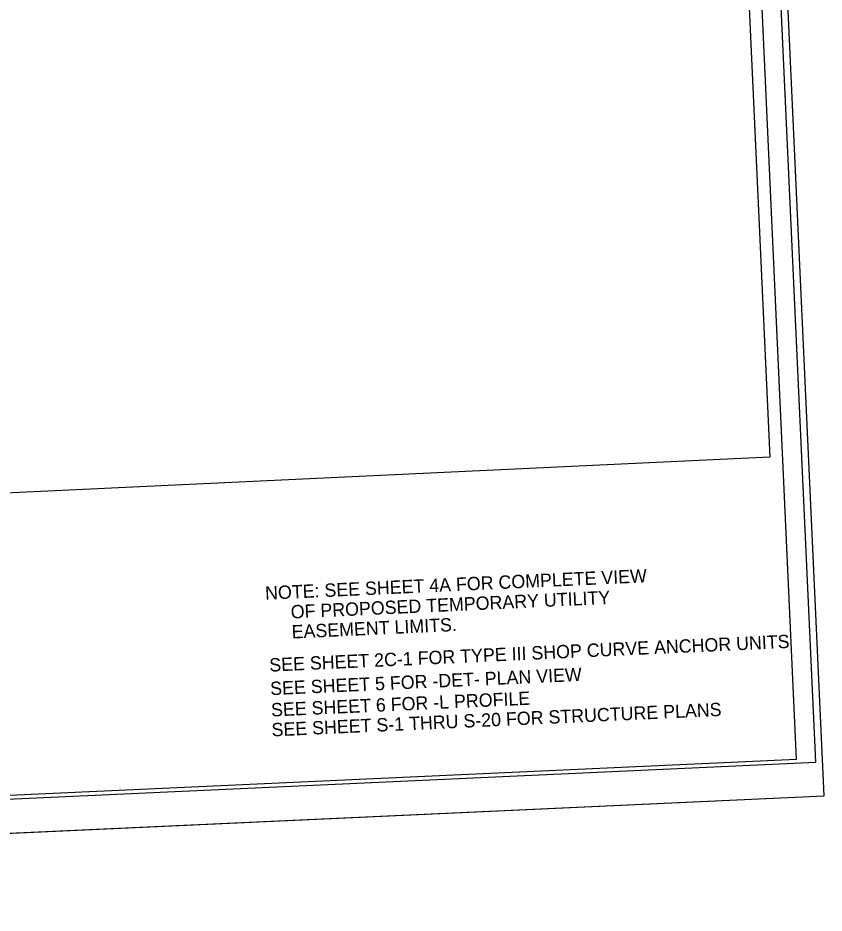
# Model space of a CAD drawing. Extents: x 1191067 to 1191874, y 892813 to 893283.
# Drawn here: x 1191598.1 to 1191809.9, y 892813.1 to 893048.3 of the extents above; entities that cross this region are included whole.
import ezdxf

# ---------------------------------------------------------------- set-up
doc = ezdxf.new("R2010")
doc.units = 0
for name, color, linetype in [('Prop DSN Text', 7, 'Continuous'), ('Sheet Border Standard 30in CELL', 7, 'Continuous'), ('Sheet Clip Boundary CELL', 7, 'Continuous'), ('Sheet Cutting Line CELL', 7, 'Continuous'), ('Sheet Plot Border Inside CELL', 7, 'Continuous'), ('Sheet Plot Border Outside CELL', 7, 'Continuous')]:
    doc.layers.add(name, color=color, linetype=linetype)

msp = doc.modelspace()

# ---------------------------------------------------------------- linework, layer by layer
at = {"layer": 'Sheet Border Standard 30in CELL'}
msp.add_lwpolyline([(1191783.48, 893273.17), (1191184.11, 893245.75), (1191203.31, 892826.19), (1191802.68, 892853.61)], close=True, dxfattribs=at)
at = {"layer": 'Sheet Clip Boundary CELL'}
msp.add_lwpolyline([(1191202.89, 892905.77), (1191187.26, 893244.08), (1191701.27, 893267.82), (1191704.06, 893207.36), (1191782.86, 893211), (1191795.71, 892932.92), (1191477.62, 892917.95)], close=True, dxfattribs=at)
at = {"layer": 'Sheet Cutting Line CELL'}
msp.add_line((1191137.03, 892813.14), (1191809.93, 892843.93), dxfattribs=at)
at = {"layer": 'Sheet Plot Border Inside CELL'}
msp.add_lwpolyline([(1191788.43, 893274.42), (1191122.53, 893243.95), (1191141.82, 892822.35), (1191807.72, 892852.82)], close=True, dxfattribs=at)
at = {"layer": 'Sheet Plot Border Outside CELL'}
msp.add_lwpolyline([(1191789.82, 893283.47), (1191116.92, 893252.68), (1191137.03, 892813.14), (1191809.93, 892843.93)], close=True, dxfattribs=at)

# ---------------------------------------------------------------- texts
at = {"layer": 'Prop DSN Text'}
for s, p in [('NOTE: SEE SHEET 4A FOR COMPLETE VIEW ', (1191663.15, 892895.46)), ('     OF PROPOSED TEMPORARY UTILITY ', (1191663.39, 892890.22)), ('     EASEMENT LIMITS. ', (1191663.63, 892884.97)), ('SEE SHEET 2C-1 FOR TYPE III SHOP CURVE ANCHOR UNITS ', (1191664.26, 892876.56)), ('SEE SHEET 5 FOR -DET- PLAN VIEW', (1191664.49, 892870.39)), ('SEE SHEET 6 FOR -L PROFILE', (1191664.71, 892864.77)), ('SEE SHEET S-1 THRU S-20 FOR STRUCTURE PLANS', (1191664.85, 892859.54))]:
    msp.add_text(s, height=3.5, rotation=2.6195, dxfattribs=at).set_placement(p)

doc.saveas('drawing.dxf')
